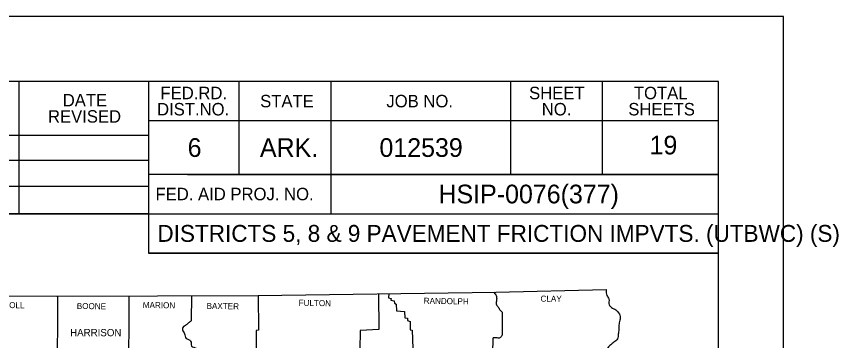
# Model space of a CAD drawing. Extents: x 840176 to 859715, y 1589036 to 1600368.
# Drawn here: x 854218 to 857388, y 1598788 to 1600036 of the extents above; entities that cross this region are included whole.
import ezdxf

# ---------------------------------------------------------------- set-up
doc = ezdxf.new("R2010")
doc.units = 0
doc.layers.add('DSN_DRFT_Border', color=7, linetype='Continuous')
doc.layers.add('SHET_Border-Text', color=7, linetype='Continuous')

msp = doc.modelspace()

# ---------------------------------------------------------------- linework, layer by layer
at = {"layer": 'DSN_DRFT_Border'}
for p, q in [((856064.8, 1598967.6), (856060.6, 1598974.6)), ((856088.4, 1598899.7), (856091.2, 1598897.1)), ((856089.4, 1598805.4), (856091.2, 1598808.7))]:
    msp.add_line(p, q, dxfattribs=at)
msp.add_lwpolyline([(840175.5, 1600035.6), (840175.5, 1589035.6), (857175.5, 1589035.6), (857175.5, 1600035.6)], close=True, dxfattribs=at)
for points in [[(853488.3, 1598959.8), (854373.4, 1598959.2), (855150.8, 1598960.7), (856067.3, 1598974.7), (856492.4, 1598984.7)], [(853989.1, 1598788.7), (854127.2, 1598784.3), (854130.3, 1598766.8), (854149.3, 1598766.2), (854148.7, 1598755.6), (854161.4, 1598752.2), (854162.7, 1598692.1), (854179.8, 1598688.4), (854181, 1598664.7), (854204.7, 1598661.6), (854205.9, 1598639.5), (854253.3, 1598634.4), (854376.5, 1598637.7), (854377.4, 1598959.2)], [(854651.9, 1598959.7), (854650, 1598626.2)], [(854892.8, 1598960.2), (854891.5, 1598863.6)], [(855150.4, 1598960.7), (855151.7, 1598827.2), (855142.7, 1598826.6), (855143.9, 1598690.3), (855105.9, 1598684.7), (855109.1, 1598648.3), (855122.1, 1598631.1), (855121.2, 1598587.9), (855046.8, 1598585.1), (855044, 1598518.5), (854976.2, 1598516.3), (854972.4, 1598434.8), (854976.5, 1598428.5), (854978.3, 1598299.1), (855095.1, 1598291.3), (855093.5, 1598002.8), (855186.9, 1598000.3), (855186.9, 1597706.5), (855113.4, 1597700.9), (855108.1, 1597636.8), (854984.6, 1597635.9)], [(855614.4, 1598967.8), (855615.4, 1598830), (855544.1, 1598826), (855542.3, 1598751.6), (855143.3, 1598753.5)], [(855654.4, 1598968.4), (855652.4, 1598951.7), (855663.3, 1598950.1), (855662.4, 1598943.9), (855675.1, 1598941.1), (855676.1, 1598932.1), (855682.3, 1598928.3), (855683.9, 1598902.2), (855715, 1598899.1), (855715.3, 1598875.1), (855726.8, 1598873.9), (855726.5, 1598864.5), (855736.5, 1598861.4), (855736.1, 1598829.7), (855744.5, 1598828.1), (855746.7, 1598756.6), (855700.4, 1598752.2), (855701, 1598737), (855687, 1598736), (855691.6, 1598453.7), (855912.3, 1598448.8), (855916, 1598009.3), (855771.9, 1598005.6), (855769.3, 1598082.6)], [(856091.2, 1598897.1), (856091.2, 1598808.7)], [(856054.1, 1598677.2), (856056.7, 1598797.9)]]:
    msp.add_lwpolyline(points, dxfattribs=at)
for points in [[(856492.4, 1598984.7), (856495.2, 1598960.7), (856502.7, 1598948.3), (856503.9, 1598925.2), (856513.2, 1598915.3), (856529.1, 1598905.6), (856543.1, 1598889.4), (856546.2, 1598870.8), (856541.9, 1598851.8), (856540.9, 1598830.6), (856538.8, 1598812), (856535.6, 1598794.8), (856522.3, 1598781.1), (856509.8, 1598771.5), (856498.3, 1598760), (856490.2, 1598747.5), (856475.6, 1598734.5), (856461.6, 1598720.8), (856450.1, 1598708.6), (856438.9, 1598693.4), (856432.9, 1598676.6), (856420.8, 1598664.4), (856410.9, 1598653.5), (856397.5, 1598638.9), (856390.9, 1598623.7), (856378.5, 1598607.2), (856375.4, 1598590.7), (856360.7, 1598557.4)], [(856064.8, 1598967.6), (856069.8, 1598954.2), (856068.8, 1598939.2), (856069.1, 1598925.9), (856076, 1598916.2), (856083.5, 1598904.7), (856088.4, 1598899.7)], [(854891.5, 1598863.6), (854881.6, 1598855.8), (854873.2, 1598848.1), (854859.8, 1598838.4), (854858.2, 1598829.7), (854862.6, 1598821.3), (854866.9, 1598814.1), (854868.8, 1598804.2), (854872.5, 1598796.1), (854881.6, 1598792.3), (854889.7, 1598785.5), (854892.1, 1598775.9), (854893.4, 1598766.5), (854901.8, 1598762.2), (854911.7, 1598758.4), (854921.4, 1598751.9), (854925.8, 1598744.1), (854926.4, 1598733.2), (854930.4, 1598725.4), (854934.8, 1598715.2), (854935.7, 1598707.1), (854934.8, 1598699), (854937.3, 1598691.2), (854944.1, 1598683.4), (854956.6, 1598679.7), (854965.6, 1598674.4), (854971.8, 1598666.6), (854967.5, 1598657.6), (854968.4, 1598649.2), (854973.1, 1598639.2)], [(856089.4, 1598805.4), (856082.2, 1598797.9), (856068.2, 1598798.3), (856056.7, 1598797.9)]]:
    msp.add_spline(points, degree=3, dxfattribs=at)
at = {"layer": 'SHET_Border-Text'}
for p, q in [((854229.2, 1599276.2), (854229.2, 1599785.6)), ((854727.5, 1599785.6), (854727.5, 1599124.6)), ((855076.3, 1599785.6), (855076.3, 1599427.8)), ((855430.2, 1599785.6), (855430.2, 1599276.2)), ((856122.8, 1599785.6), (856122.8, 1599427.8)), ((856476.7, 1599785.6), (856476.7, 1599427.8)), ((856925.5, 1599634), (854727.5, 1599634)), ((856925.5, 1599635.1), (856925.5, 1599635.1)), ((853731, 1599578.4), (854727.5, 1599578.4)), ((853731, 1599482.4), (854727.5, 1599482.4)), ((856925.5, 1599427.8), (854727.5, 1599427.8)), ((854878.4, 1599427.8), (856925.5, 1599427.8)), ((853731, 1599382.4), (854727.5, 1599382.4)), ((854727.5, 1599276.2), (853731, 1599276.2)), ((854727.5, 1599276.2), (856925.5, 1599276.2)), ((856925.5, 1599124.6), (854727.5, 1599124.6))]:
    msp.add_line(p, q, dxfattribs=at)
for points in [[(840175.5, 1589035.6), (857175.5, 1589035.6), (857175.5, 1600035.6), (840175.5, 1600035.6)], [(840425.5, 1589285.6), (856925.5, 1589285.6), (856925.5, 1599785.6), (840425.5, 1599785.6)], [(852734.4, 1599276.2), (854727.5, 1599276.2), (854727.5, 1599124.6), (856925.5, 1599124.6), (856925.5, 1599785.6), (852734.4, 1599785.6)]]:
    msp.add_lwpolyline(points, close=True, dxfattribs=at)

# ---------------------------------------------------------------- texts
at = {"layer": 'DSN_DRFT_Border'}
for s, height, p in [('FED.RD.', 48, (854773.6, 1599717)), ('SHEET', 48, (856195, 1599717)), ('TOTAL', 48, (856599.2, 1599717)), ('DATE', 48, (854396.8, 1599689.2)), ('STATE', 48, (855158, 1599685.8)), ('JOB NO.', 48, (855644.8, 1599685.8)), ('DIST.NO.', 48, (854760.5, 1599654.6)), ('NO.', 48, (856243.9, 1599654.6)), ('SHEETS', 48, (856577.7, 1599654.6)), ('REVISED', 48, (854339.9, 1599626.8)), ('19', 72, (856659.6, 1599504.4)), ('6', 72, (854878.4, 1599494.9)), ('ARK.', 72, (855157.2, 1599494.9)), ('012539', 72, (855618, 1599494.9)), ('HSIP-0076(377)', 72, (855845.7, 1599316)), ('FED. AID PROJ. NO.', 48, (854754.5, 1599328)), ('DISTRICTS 5, 8 & 9 PAVEMENT FRICTION IMPVTS. (UTBWC) (S)', 65, (854761.8, 1599167.9)), ('HARRISON', 28.01, (854425.3, 1598804.5))]:
    msp.add_text(s, height=height, dxfattribs=at).set_placement(p)
for s, rotation, p in [('FULTON', 359.282, (855306.3, 1598921.5)), ('RANDOLPH', 359.2573, (855788.7, 1598929.3)), ('CLAY', 359.3364, (856239.2, 1598937.7)), ('CARROLL', 359.267, (854101.7, 1598914)), ('BOONE', 359.3139, (854450.9, 1598909.4)), ('MARION', 359.2237, (854705.4, 1598913.4)), ('BAXTER', 359.2892, (854951.4, 1598909.7))]:
    msp.add_text(s, height=23.34, rotation=rotation, dxfattribs=at).set_placement(p)

doc.saveas('drawing.dxf')
